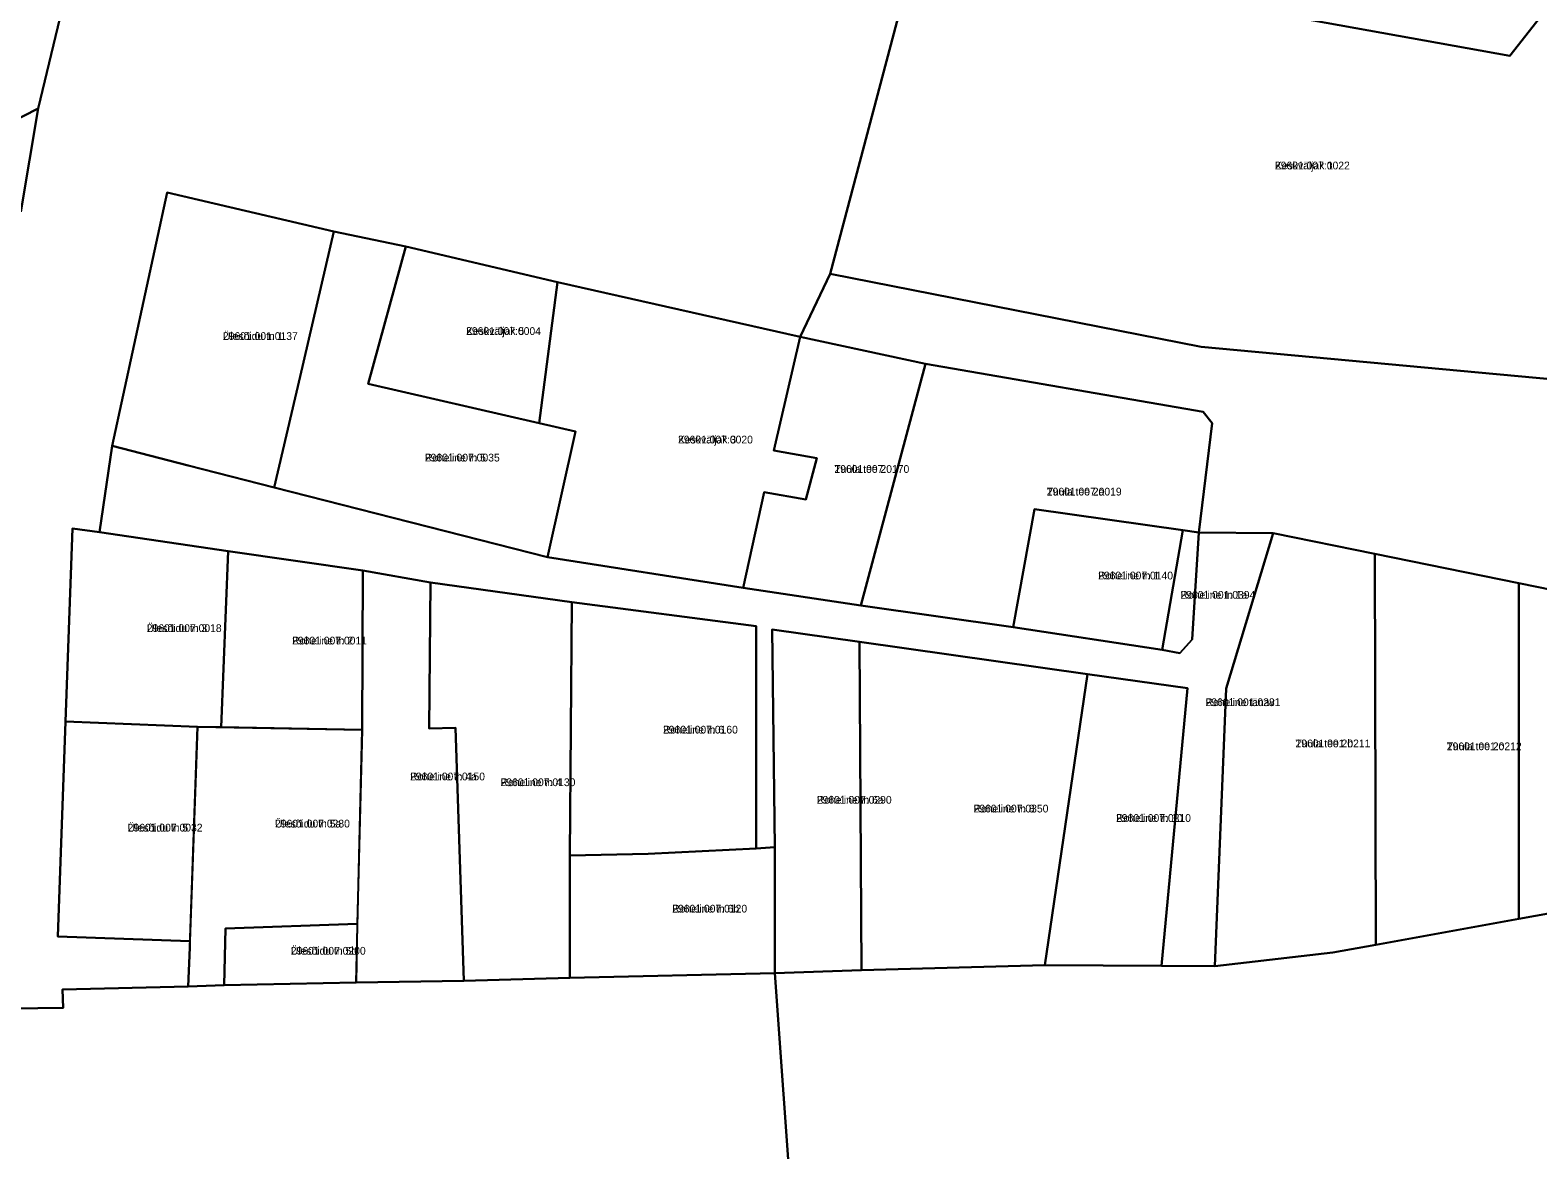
# Model space of a CAD drawing. Extents: x 518839 to 525192, y 6573164 to 6576561.
# Drawn here: x 524230.2 to 524522.2, y 6574299.5 to 6574516.4 of the extents above; entities that cross this region are included whole.
import ezdxf

# ---------------------------------------------------------------- set-up
doc = ezdxf.new("R2010")
doc.units = 0
for name, color, linetype in [('L_AADRESS', 7, 'Continuous'), ('PIIR', 7, 'Continuous'), ('TUNNUS', 7, 'Continuous')]:
    doc.layers.add(name, color=color, linetype=linetype)

msp = doc.modelspace()

# ---------------------------------------------------------------- linework, layer by layer
at = {"layer": 'PIIR'}
for points in [[(524401.81, 6574532.13), (524431.89, 6574562.69), (524434.43, 6574559.64), (524457.58, 6574545.58), (524460.17, 6574547.21), (524464.93, 6574539.89), (524516.34, 6574529.97), (524555.31, 6574522.82), (524565.29, 6574520.99), (524564.47, 6574513.44), (524561.67, 6574485.75), (524560.44, 6574467.33), (524557.14, 6574442.73), (524546.99, 6574446.75), (524554.43, 6574509.27), (524547.65, 6574515.75), (524523.42, 6574519.87), (524516.79, 6574511.45)], [(524165.75, 6574537.51), (524236.37, 6574520.54), (524231.72, 6574501.21), (524205.78, 6574488.03), (524201.49, 6574497.08), (524191.56, 6574499.32), (524167.64, 6574487.97), (524165.87, 6574493.59), (524157.06, 6574490.89), (524159.65, 6574484.94), (524164.05, 6574486.32), (524171.13, 6574471.57), (524163.19, 6574467.21), (524149.18, 6574496.1), (524149.94, 6574510.31), (524161.44, 6574518.56)], [(524401.81, 6574532.13), (524516.79, 6574511.45), (524523.42, 6574519.87), (524547.65, 6574515.75), (524554.43, 6574509.27), (524546.99, 6574446.75), (524456.99, 6574455.07), (524385.14, 6574469.23)], [(524246.06, 6574435.88), (524256.75, 6574484.99), (524289, 6574477.44), (524282.47, 6574449.33), (524277.46, 6574427.8), (524260.77, 6574432.1)], [(524289, 6574477.44), (524302.96, 6574474.5), (524295.63, 6574447.89), (524328.76, 6574440.27), (524335.82, 6574438.7), (524330.38, 6574414.36), (524277.46, 6574427.8), (524282.47, 6574449.33)], [(524332.35, 6574467.6), (524328.76, 6574440.27), (524295.63, 6574447.89), (524302.96, 6574474.5)], [(524335.82, 6574438.7), (524328.76, 6574440.27), (524332.35, 6574467.6), (524379.36, 6574457.02), (524374.21, 6574434.99), (524382.58, 6574433.52), (524380.45, 6574425.53), (524372.38, 6574426.93), (524368.32, 6574408.38), (524330.38, 6574414.36)], [(524372.38, 6574426.93), (524380.45, 6574425.53), (524382.58, 6574433.52), (524374.21, 6574434.99), (524379.36, 6574457.02), (524403.59, 6574451.81), (524391.11, 6574404.95), (524368.32, 6574408.38)], [(524403.59, 6574451.81), (524457.39, 6574442.51), (524459.1, 6574440.29), (524456.53, 6574419.13), (524453.47, 6574419.57), (524424.71, 6574423.64), (524420.61, 6574400.75), (524391.11, 6574404.95)], [(524246.06, 6574435.88), (524260.77, 6574432.1), (524277.46, 6574427.8), (524330.38, 6574414.36), (524368.32, 6574408.38), (524391.11, 6574404.95), (524420.61, 6574400.75), (524449.42, 6574396.41), (524452.88, 6574395.74), (524455.26, 6574398.42), (524456.53, 6574419.13), (524470.93, 6574418.97), (524461.83, 6574388.89), (524459.67, 6574335.09), (524449.29, 6574335.16), (524454.32, 6574388.97), (524435, 6574391.69), (524390.81, 6574397.94), (524373.88, 6574400.33), (524374.4, 6574358.14), (524370.81, 6574357.9), (524370.82, 6574400.99), (524335.1, 6574405.59), (524307.72, 6574409.4), (524294.65, 6574411.74), (524268.53, 6574415.5), (524243.61, 6574419.16)], [(524453.47, 6574419.57), (524449.42, 6574396.41), (524420.61, 6574400.75), (524424.71, 6574423.64)], [(524238.4, 6574419.92), (524243.61, 6574419.16), (524268.53, 6574415.5), (524267.21, 6574381.41), (524262.58, 6574381.5), (524237.03, 6574382.48)], [(524455.26, 6574398.42), (524452.88, 6574395.74), (524449.42, 6574396.41), (524453.47, 6574419.57), (524456.53, 6574419.13)], [(524461.83, 6574388.89), (524470.93, 6574418.97), (524490.62, 6574414.97), (524490.84, 6574339.28), (524482.48, 6574337.78), (524459.67, 6574335.09)], [(524294.65, 6574411.74), (524294.47, 6574380.89), (524267.21, 6574381.41), (524268.53, 6574415.5)], [(524490.84, 6574339.28), (524490.62, 6574414.97), (524518.5, 6574409.32), (524518.51, 6574344.28)], [(524307.5, 6574381.17), (524312.6, 6574381.28), (524314.2, 6574332.27), (524293.35, 6574331.96), (524294.47, 6574380.89), (524294.65, 6574411.74), (524307.72, 6574409.4)], [(524334.7, 6574356.58), (524334.71, 6574332.87), (524314.2, 6574332.27), (524312.6, 6574381.28), (524307.5, 6574381.17), (524307.72, 6574409.4), (524335.1, 6574405.59)], [(524518.51, 6574344.28), (524518.5, 6574409.32), (524535.31, 6574405.91), (524546.16, 6574404.26), (524546.14, 6574349.24)], [(524335.1, 6574405.59), (524370.82, 6574400.99), (524370.81, 6574357.9), (524349.91, 6574356.9), (524334.7, 6574356.58)], [(524390.81, 6574397.94), (524391.22, 6574334.37), (524374.42, 6574333.78), (524374.41, 6574357.61), (524374.4, 6574358.14), (524373.88, 6574400.33)], [(524390.81, 6574397.94), (524435, 6574391.69), (524426.7, 6574335.33), (524391.22, 6574334.37)], [(524435, 6574391.69), (524454.32, 6574388.97), (524449.29, 6574335.16), (524426.7, 6574335.33)], [(524237.03, 6574382.48), (524262.58, 6574381.5), (524261.14, 6574339.95), (524235.58, 6574340.88)], [(524267.77, 6574331.41), (524260.77, 6574331.17), (524261.1, 6574338.72), (524262.58, 6574381.5), (524294.47, 6574380.89), (524293.54, 6574343.29), (524268.04, 6574342.41)], [(524374.4, 6574358.14), (524374.41, 6574357.61), (524374.42, 6574333.78), (524334.71, 6574332.87), (524334.7, 6574356.58), (524349.91, 6574356.9), (524370.81, 6574357.9)], [(524267.77, 6574331.41), (524268.04, 6574342.41), (524293.54, 6574343.29), (524293.35, 6574331.96)]]:
    msp.add_lwpolyline(points, close=True, dxfattribs=at)
for points in [[(524228.42, 6574481.2), (524231.72, 6574501.21), (524236.37, 6574520.54), (524165.75, 6574537.51)], [(524401.81, 6574532.13), (524385.14, 6574469.23), (524379.36, 6574457.02), (524332.35, 6574467.6), (524302.96, 6574474.5), (524289, 6574477.44), (524256.75, 6574484.99), (524246.06, 6574435.88), (524243.61, 6574419.16), (524238.4, 6574419.92), (524237.03, 6574382.48), (524235.58, 6574340.88), (524261.14, 6574339.95), (524261.1, 6574338.72), (524260.77, 6574331.17), (524236.47, 6574330.63), (524236.58, 6574327.02), (524221.73, 6574326.86)], [(524205.78, 6574488.03), (524231.72, 6574501.21), (524228.42, 6574481.2)], [(524535.31, 6574405.91), (524518.5, 6574409.32), (524490.62, 6574414.97), (524470.93, 6574418.97), (524456.53, 6574419.13), (524459.1, 6574440.29), (524457.39, 6574442.51), (524403.59, 6574451.81), (524379.36, 6574457.02), (524385.14, 6574469.23), (524456.99, 6574455.07), (524546.99, 6574446.75)], [(524377.78, 6574286.88), (524374.42, 6574333.78), (524391.22, 6574334.37), (524426.7, 6574335.33), (524449.29, 6574335.16), (524459.67, 6574335.09), (524482.48, 6574337.78), (524490.84, 6574339.28), (524518.51, 6574344.28), (524546.14, 6574349.24), (524578.79, 6574355.29), (524622.34, 6574364.41), (524671.89, 6574377.53), (524674.63, 6574378.38), (524674.19, 6574379.29), (524700.15, 6574392.87), (524710.26, 6574396.01), (524711.59, 6574396.58), (524721.62, 6574401.47), (524735.93, 6574408.31), (524753.73, 6574417.26), (524778.37, 6574429.72), (524790.19, 6574434.06)], [(524221.73, 6574326.86), (524236.58, 6574327.02), (524236.47, 6574330.63), (524260.77, 6574331.17), (524267.77, 6574331.41), (524293.35, 6574331.96), (524314.2, 6574332.27), (524334.71, 6574332.87), (524374.42, 6574333.78), (524377.78, 6574286.88)]]:
    msp.add_lwpolyline(points, dxfattribs=at)

# ---------------------------------------------------------------- texts
at = {"layer": 'L_AADRESS'}
for s, p in [('Keskväljak 1', (524471.28, 6574489.44)), ('Ülesõidu tn 1', (524267.53, 6574456.41)), ('Keskväljak 5', (524314.63, 6574457.38)), ('Keskväljak 3', (524355.67, 6574436.36)), ('Roheline tn 5', (524306.64, 6574432.87)), ('Tuula tee 2', (524385.96, 6574430.66)), ('Tuula tee 2a', (524427.09, 6574426.28)), ('Roheline tn 1', (524437.04, 6574410.03)), ('Roheline tn 1a', (524452.98, 6574406.29)), ('Ülesõidu tn 3', (524252.78, 6574399.84)), ('Roheline tn 2', (524280.93, 6574397.43)), ('Roheline tänav', (524457.84, 6574385.49)), ('Roheline tn 6', (524352.76, 6574380.18)), ('Tuula tee 2b', (524475.26, 6574377.51)), ('Tuula tee 2c', (524504.56, 6574376.95)), ('Roheline tn 4a', (524303.78, 6574371.11)), ('Roheline tn 4', (524321.3, 6574369.99)), ('Roheline tn 6a', (524382.55, 6574366.59)), ('Roheline tn 8', (524412.91, 6574364.89)), ('Ülesõidu tn 5a', (524277.62, 6574361.98)), ('Roheline tn 10', (524440.51, 6574363.07)), ('Ülesõidu tn 5', (524249.08, 6574361.2)), ('Roheline tn 6b', (524354.56, 6574345.51)), ('Ülesõidu tn 5b', (524280.68, 6574337.35))]:
    msp.add_text(s, height=1.5, dxfattribs=at).set_placement(p)
at = {"layer": 'TUNNUS'}
for s, p in [('29601:007:0022', (524471.28, 6574489.44)), ('29601:001:0137', (524267.53, 6574456.41)), ('29601:007:0004', (524314.63, 6574457.38)), ('29601:007:0020', (524355.67, 6574436.36)), ('29601:007:0035', (524306.64, 6574432.87)), ('29601:007:0170', (524385.96, 6574430.66)), ('29601:007:0019', (524427.09, 6574426.28)), ('29601:007:0140', (524437.04, 6574410.03)), ('29601:001:0394', (524452.98, 6574406.29)), ('29601:007:0018', (524252.78, 6574399.84)), ('29601:007:0011', (524280.93, 6574397.43)), ('29601:001:0281', (524457.84, 6574385.49)), ('29601:007:0160', (524352.76, 6574380.18)), ('29601:001:0211', (524475.26, 6574377.51)), ('29601:001:0212', (524504.56, 6574376.95)), ('29601:007:0150', (524303.78, 6574371.11)), ('29601:007:0130', (524321.3, 6574369.99)), ('29601:007:0290', (524382.55, 6574366.59)), ('29601:007:0350', (524412.91, 6574364.89)), ('29601:007:0280', (524277.62, 6574361.98)), ('29601:007:0210', (524440.51, 6574363.07)), ('29601:007:0032', (524249.08, 6574361.2)), ('29601:007:0120', (524354.56, 6574345.51)), ('29601:007:0200', (524280.68, 6574337.35))]:
    msp.add_text(s, height=1.5, dxfattribs=at).set_placement(p)

doc.saveas('drawing.dxf')
